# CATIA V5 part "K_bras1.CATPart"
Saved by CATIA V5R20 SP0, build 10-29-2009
Part number: bras1
Publications: "Plan.1", "Point_origine", "Plan.2", "Droite.1"
Bounding box of the stored display mesh (mm): x -50 to 50, y -49.988 to 49.988, z -10 to 175
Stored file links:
  G:\Khaled_CFAO_2011\SIL\SIL_GR2\pfradet\pfradet\Khaled\CAD_ThinkMOTION\K_bras1.CATPart
  U:\TNHIKMOTION\ass_cutting_device.CATProduct
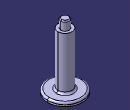
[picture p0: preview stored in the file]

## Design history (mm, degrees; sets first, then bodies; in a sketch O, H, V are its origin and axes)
External parameters (linked from other documents)
  External.Longueur_bras1 = 150 mm
Plane1: linked copy from another document
Set1
  Point1 "Point_origine": linked copy from another document
  Line1: linked copy from another document
Set2
  Plane2: type Offset, RefPlane xy-plane, Offset 10, reversed
Body1 (main body)
  Sketch1 on xy-plane, origin (0, 0, 0), H (1, 0, 0), V (0, 1, 0)
    circle A1 centre (0, 0) radius 20
  Pad1: profile Sketch1, direction (0, 0, 1), length 150 {= External.Longueur_bras1}
  Sketch2 on Plane2, origin (0, 0, -10), H (1, 0, 0), V (0, 1, 0)
    circle A1 centre (0, 0) radius 50
  Pad2: profile Sketch2, direction (0, 0, 1), length 10
  Fillet1: radius 5, on end face of Pad2
  Sketch3 on end face of Pad1, origin (0, 0, 150), H (1, 0, 0), V (0, 1, 0)
    circle A1 centre (0, 0) radius 12
  Pad3: profile Sketch3, direction (0, 0, 1), length 25
  Chamfer1: length 3, angle 45, on edge [face of Pad3 from Sketch3.A1 | end face of Pad3]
